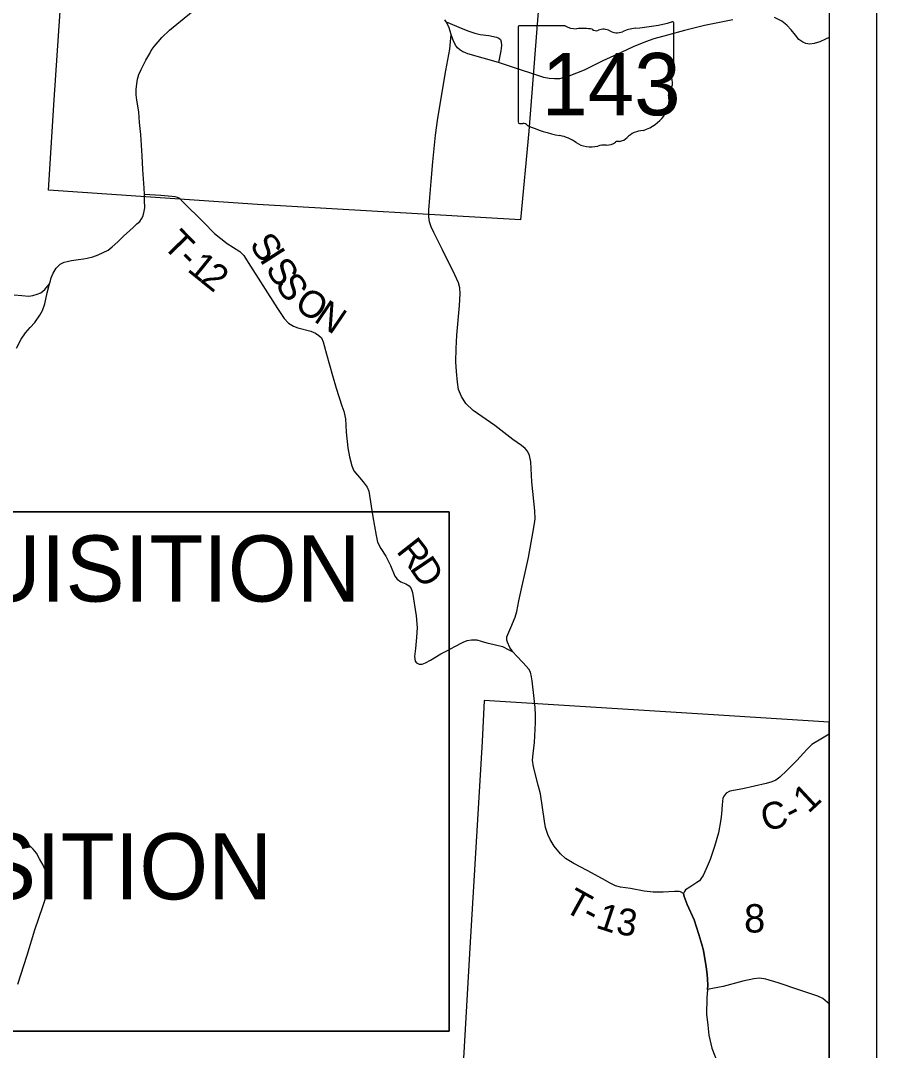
# Model space of a CAD drawing. Extents: x 0 to 34, y 0 to 22.
# Drawn here: x 7.19 to 9, y 15.883 to 18.062 of the extents above; entities that cross this region are included whole.
import ezdxf

# ---------------------------------------------------------------- set-up
doc = ezdxf.new("R2010")
doc.units = 0
for name, color, linetype in [('GM_X_Corporation', 7, 'Continuous'), ('GM_X_County_Road', 7, 'Continuous'), ('GM_X_County_Road_Text', 7, 'Continuous'), ('GM_X_Section_Text', 7, 'Continuous'), ('GM_X_State_Location', 7, 'Continuous'), ('GM_X_State_Route', 7, 'Continuous'), ('GM_X_State_Shield', 7, 'Continuous'), ('GM_X_Township_Road', 7, 'Continuous'), ('GM_X_Township_Road_Text', 7, 'Continuous'), ('SH_Data', 7, 'Continuous'), ('SH_Text', 7, 'Continuous')]:
    doc.layers.add(name, color=color, linetype=linetype)

msp = doc.modelspace()

# ---------------------------------------------------------------- linework, layer by layer
at = {"layer": 'GM_X_Corporation'}
for points in [[(7.3179, 18.7214), (8.3303, 18.6644), (8.2967, 18.2357), (8.2648, 17.8281), (8.2474, 17.6405), (7.6907, 17.673), (7.2488, 17.7032), (7.2611, 17.894), (7.2923, 18.3534)], [(8.9, 15.5562), (8.9, 16.5775), (8.644, 16.594), (8.1703, 16.6232), (8.1663, 16.5368), (8.1403, 16.1), (8.1117, 15.6084)]]:
    msp.add_lwpolyline(points, close=True, dxfattribs=at)
at = {"layer": 'GM_X_County_Road'}
for points in [[(7.4519, 17.6946), (7.4514, 17.7073), (7.4484, 17.7469), (7.4468, 17.7761), (7.4442, 17.8206), (7.4416, 17.846), (7.4398, 17.8692), (7.4358, 17.8939), (7.4342, 17.9049), (7.4346, 17.9163), (7.4358, 17.9278), (7.4374, 17.9381), (7.4402, 17.9476), (7.4449, 17.9584), (7.455, 17.9784), (7.4633, 17.9926), (7.466, 17.9986), (7.4724, 18.0074), (7.4808, 18.0172), (7.489, 18.0261), (7.5051, 18.0415), (7.528, 18.0608), (7.5551, 18.0823)], [(7.2513, 17.5047), (7.2531, 17.5116), (7.2549, 17.5176), (7.2587, 17.5274), (7.2652, 17.538), (7.2736, 17.5463), (7.2824, 17.5505), (7.2888, 17.5522), (7.2976, 17.5541), (7.3125, 17.5562), (7.3228, 17.5576), (7.3305, 17.5592), (7.3427, 17.5624), (7.3544, 17.5666), (7.3648, 17.5715), (7.3751, 17.5764), (7.384, 17.5832), (7.3954, 17.594), (7.4082, 17.6068), (7.4204, 17.6173), (7.4291, 17.6246), (7.4361, 17.6318), (7.4424, 17.637), (7.4457, 17.6426), (7.4487, 17.6477), (7.451, 17.6554), (7.4526, 17.6659), (7.4524, 17.6818), (7.4519, 17.6946)], [(7.1811, 17.3688), (7.1912, 17.3879), (7.2005, 17.4014), (7.2105, 17.4123), (7.2203, 17.4235), (7.2309, 17.4387), (7.2364, 17.4486), (7.2413, 17.4625), (7.2463, 17.4857), (7.2513, 17.5047)], [(8.9, 16.5523), (8.8858, 16.5441), (8.8634, 16.5303), (8.8536, 16.5209), (8.846, 16.5123), (8.8315, 16.4967), (8.8109, 16.4752), (8.7961, 16.4617), (8.7875, 16.4551), (8.7792, 16.4515), (8.7666, 16.4478), (8.7172, 16.4364), (8.6899, 16.4316), (8.6822, 16.4272), (8.6778, 16.422), (8.6755, 16.4168), (8.6736, 16.4025), (8.6722, 16.3841), (8.6707, 16.3719), (8.6659, 16.3439), (8.6579, 16.3145), (8.6482, 16.2875), (8.6421, 16.2724), (8.6337, 16.2532), (8.6286, 16.2461), (8.6257, 16.2419), (8.62, 16.2383), (8.6053, 16.2288), (8.5966, 16.2227), (8.5938, 16.2197), (8.5922, 16.2151)], [(7.1844, 16.0237), (7.2038, 16.0846), (7.2203, 16.1385), (7.2367, 16.188), (7.2437, 16.2065), (7.2488, 16.2243), (7.2498, 16.2357), (7.2483, 16.2462), (7.2448, 16.2588), (7.2378, 16.2753), (7.2301, 16.2889), (7.2239, 16.3003), (7.2169, 16.309), (7.2071, 16.3183), (7.1996, 16.3232), (7.1909, 16.327), (7.1802, 16.3307)], [(8.5922, 16.2151), (8.5932, 16.2088), (8.5996, 16.1917), (8.6148, 16.1598), (8.6248, 16.1285), (8.6309, 16.1074), (8.6346, 16.0946), (8.6398, 16.0599), (8.6424, 16.0436), (8.6426, 16.0341), (8.6433, 16.0212), (8.6428, 16.0121)], [(8.6428, 16.0121), (8.6415, 15.9944), (8.6407, 15.9598), (8.6432, 15.9369), (8.6456, 15.9158), (8.6518, 15.8883), (8.6643, 15.8553), (8.6681, 15.8451), (8.6695, 15.8379), (8.6687, 15.8305), (8.6671, 15.8238), (8.6624, 15.8161), (8.6534, 15.8085), (8.6369, 15.7985), (8.6126, 15.7832), (8.5958, 15.7721), (8.567, 15.7446), (8.557, 15.7324), (8.5528, 15.7256), (8.547, 15.7123), (8.5284, 15.6477), (8.5247, 15.6238), (8.522, 15.612)]]:
    msp.add_lwpolyline(points, dxfattribs=at)
at = {"layer": 'GM_X_State_Route'}
for points in [[(8.6961, 18.0633), (8.6367, 18.0516), (8.5942, 18.0408), (8.558, 18.0314), (8.5294, 18.023), (8.5117, 18.0172), (8.4858, 18.0066), (8.46, 17.9945), (8.4213, 17.9765), (8.3817, 17.9567), (8.3497, 17.9441), (8.3295, 17.9389), (8.3189, 17.9385), (8.3079, 17.9391), (8.2964, 17.9416), (8.28, 17.947), (8.2386, 17.9607), (8.2005, 17.973), (8.136, 17.9916), (8.1297, 17.9942), (8.1253, 17.9958), (8.119, 17.9997), (8.1143, 18.004), (8.1096, 18.0099), (8.1046, 18.0205), (8.101, 18.0322), (8.0965, 18.0467), (8.0931, 18.0546), (8.0901, 18.0591), (8.087, 18.0635)], [(8.9, 18.0258), (8.8927, 18.0228), (8.8803, 18.017), (8.8684, 18.0131), (8.8592, 18.012), (8.8508, 18.0134), (8.8441, 18.0165), (8.8362, 18.0219), (8.8286, 18.0311), (8.8198, 18.0426), (8.8108, 18.0525), (8.7998, 18.061), (8.7847, 18.0685)]]:
    msp.add_lwpolyline(points, dxfattribs=at)
at = {"layer": 'GM_X_State_Shield'}
for p, q in [((8.2422, 18.0476), (8.2422, 17.8475)), ((8.342, 18.051), (8.2454, 18.051)), ((8.5718, 17.9513), (8.5718, 18.056)), ((8.5718, 17.9513), (8.5718, 17.9513))]:
    msp.add_line(p, q, dxfattribs=at)
for centre, major_axis, start_param, end_param in [((8.246, 18.048), (0.00382, 0), 1.712693, 3.28349), ((8.365, 18.0742), (0.037, 0), 4.042523, 4.731795), ((8.3772, 17.9387), (0.133, 0), 1.404758, 1.657858), ((8.4074, 18.049), (0.0107, 0), 3.836095, 5.185415), ((8.4231, 18.0259), (0.0222, 0), 0.950623, 2.079405), ((8.4518, 18.0576), (0.0267, 0), 4.081561, 5.145723), ((8.499, 17.9899), (0.0703, 0), 1.699011, 2.107814), ((8.4544, 18.3238), (0.3495, 0), 4.814394, 5.042369), ((8.5681, 18.0564), (0.00367, 0), 6.141152, 7.989035), ((8.5709, 17.9436), (0.00568, 0), 1.883978, 3.671073), ((8.5348, 17.9304), (0.0341, 0), 5.934695, 6.695948), ((8.5679, 17.9509), (0.00393, 0), 5.05454, 6.418171), ((8.5849, 17.9075), (0.0248, 0), 2.387724, 3.262537), ((8.474, 17.8942), (0.0874, 0), 5.101752, 6.440018), ((8.246, 17.847), (0.00385, 0), 3.00124, 4.508301), ((8.2466, 17.8675), (0.0294, 0), 4.665946, 4.897461), ((8.2526, 17.8359), (0.0106, 0), 0.519207, 1.627899), ((8.3864, 18.0157), (0.2524, 0), 4.195997, 4.488961), ((8.5108, 17.7913), (0.0479, 0), 1.647645, 2.488434), ((8.3112, 17.7575), (0.079, 0), 0.823519, 1.323587), ((8.3966, 17.8349), (0.0501, 0), 4.026481, 4.996735), ((8.4292, 17.8199), (0.0267, 0), 4.691044, 5.507374), ((8.4534, 17.8005), (0.00752, 0), 1.147584, 2.315152), ((8.4502, 17.8281), (0.0282, 0), 4.937069, 5.64225), ((8.4256, 17.7657), (0.0412, 0), 1.495662, 1.94098)]:
    msp.add_ellipse(centre, major_axis=major_axis, ratio=0.8, start_param=start_param, end_param=end_param, dxfattribs=at)
at = {"layer": 'GM_X_Township_Road'}
for points in [[(8.0901, 18.0591), (8.1251, 18.0447), (8.1381, 18.0397), (8.1505, 18.0355), (8.1622, 18.0328), (8.1801, 18.0301), (8.1962, 18.027), (8.2018, 18.0248), (8.2049, 18.0216), (8.2067, 18.017), (8.2069, 18.0095), (8.2054, 17.998), (8.2015, 17.9767), (8.2005, 17.973)], [(8.5922, 16.2151), (8.5858, 16.2185), (8.5829, 16.2194), (8.5729, 16.2192), (8.5491, 16.2179), (8.5276, 16.2181), (8.5089, 16.2203), (8.4802, 16.2255), (8.4586, 16.2288), (8.4481, 16.2316), (8.4366, 16.2368), (8.4204, 16.2463), (8.388, 16.2637), (8.36, 16.2789), (8.3426, 16.2891), (8.3316, 16.2989), (8.3185, 16.3154), (8.3103, 16.3293), (8.3051, 16.3399), (8.3004, 16.3546), (8.2981, 16.3685), (8.2893, 16.4263), (8.2849, 16.4443), (8.2747, 16.4834), (8.2728, 16.497), (8.2738, 16.5105), (8.2767, 16.535), (8.2788, 16.5773), (8.279, 16.5928), (8.2782, 16.6084), (8.2765, 16.6279), (8.2717, 16.6652), (8.2706, 16.6733), (8.2682, 16.6835), (8.265, 16.69), (8.2526, 16.7035), (8.2389, 16.718), (8.2313, 16.7267), (8.2248, 16.736), (8.22, 16.7466), (8.2187, 16.7512), (8.2181, 16.7579), (8.2202, 16.7634), (8.2268, 16.7779), (8.2363, 16.7998), (8.2395, 16.8115), (8.2441, 16.8343), (8.2639, 16.9264), (8.2736, 16.9772), (8.2767, 16.998), (8.2782, 17.0082), (8.2777, 17.0249), (8.2713, 17.0859), (8.2689, 17.1284), (8.2663, 17.1421), (8.2623, 17.1508), (8.2574, 17.1566), (8.2495, 17.1631), (8.2313, 17.176), (8.1927, 17.2053), (8.1474, 17.2368), (8.1319, 17.2517), (8.1224, 17.2667), (8.1165, 17.2812), (8.1137, 17.2969), (8.1119, 17.3197), (8.1108, 17.3401), (8.1113, 17.3685), (8.1128, 17.3961), (8.1184, 17.4594), (8.1195, 17.4842), (8.1189, 17.4968), (8.1163, 17.507), (8.1084, 17.5239), (8.0822, 17.5766), (8.0638, 17.6139), (8.0584, 17.6258), (8.0551, 17.6361), (8.0533, 17.6467), (8.0535, 17.6606), (8.0557, 17.6875), (8.0583, 17.7218), (8.0616, 17.7628), (8.0676, 17.8195), (8.0726, 17.8555), (8.0891, 17.956), (8.0976, 18.0015), (8.101, 18.0322)], [(7.2513, 17.5047), (7.2531, 17.5116), (7.2549, 17.5176), (7.2587, 17.5274), (7.2652, 17.538), (7.2736, 17.5463), (7.2824, 17.5505), (7.2888, 17.5522), (7.2976, 17.5541), (7.3125, 17.5562), (7.3228, 17.5576), (7.3305, 17.5592), (7.3427, 17.5624), (7.3544, 17.5666), (7.3648, 17.5715), (7.3751, 17.5764), (7.384, 17.5832), (7.3954, 17.594), (7.4082, 17.6068), (7.4204, 17.6173), (7.4291, 17.6246), (7.4361, 17.6318), (7.4424, 17.637), (7.4457, 17.6426), (7.4487, 17.6477), (7.451, 17.6554), (7.4526, 17.6659), (7.4524, 17.6818), (7.4519, 17.6946)], [(7.4519, 17.6946), (7.4864, 17.6925), (7.5098, 17.6904), (7.5159, 17.6899), (7.5212, 17.6887), (7.5261, 17.686), (7.5334, 17.6785), (7.5767, 17.6357), (7.6003, 17.6112), (7.6267, 17.5902), (7.6536, 17.5731), (7.6625, 17.565), (7.6713, 17.5502), (7.7337, 17.453), (7.7475, 17.4318), (7.7563, 17.422), (7.7673, 17.4156), (7.7766, 17.4122), (7.8042, 17.4046), (7.814, 17.4006), (7.8209, 17.396), (7.8266, 17.391), (7.8302, 17.3824), (7.8371, 17.356), (7.8497, 17.3112), (7.8574, 17.2843), (7.8693, 17.2471), (7.8736, 17.2359), (7.8774, 17.2197), (7.8788, 17.1911), (7.8819, 17.1578), (7.8857, 17.1389), (7.8905, 17.1199), (7.8945, 17.1096), (7.9145, 17.0858), (7.9229, 17.0748), (7.9262, 17.0663), (7.9348, 17.0124), (7.9417, 16.9726), (7.945, 16.9583), (7.952, 16.945), (7.9624, 16.9288), (7.972, 16.9088), (7.9815, 16.8868), (7.9865, 16.8804), (7.9944, 16.8749), (8.0046, 16.8704), (8.012, 16.8659), (8.0158, 16.8602), (8.0187, 16.8521), (8.0265, 16.8025), (8.0287, 16.778), (8.0272, 16.7565), (8.0251, 16.7334), (8.0234, 16.7165), (8.0244, 16.7069), (8.0275, 16.7029), (8.033, 16.7005), (8.0392, 16.7005), (8.0464, 16.7029), (8.0567, 16.709), (8.0785, 16.722), (8.093, 16.7291), (8.1087, 16.7377), (8.1259, 16.7473), (8.1342, 16.7508), (8.1435, 16.752), (8.1547, 16.7517), (8.1642, 16.7491), (8.1762, 16.7458), (8.1919, 16.742), (8.209, 16.7379), (8.2226, 16.7305), (8.2313, 16.7267)], [(7.1763, 17.4815), (7.1926, 17.48), (7.2071, 17.4791), (7.2161, 17.4803), (7.2248, 17.4833), (7.233, 17.4863), (7.2413, 17.4933), (7.2513, 17.5047)], [(8.6428, 16.0121), (8.6433, 16.0212), (8.6426, 16.0341), (8.6424, 16.0436), (8.6398, 16.0599), (8.6346, 16.0946), (8.6309, 16.1074), (8.6248, 16.1285), (8.6148, 16.1598), (8.5996, 16.1917), (8.5932, 16.2088), (8.5922, 16.2151)], [(8.9, 15.9816), (8.8967, 15.9848), (8.8868, 15.9934), (8.876, 15.9982), (8.8631, 16.0025), (8.8358, 16.0118), (8.7925, 16.0262), (8.7665, 16.0343), (8.7531, 16.036), (8.7405, 16.0345), (8.7175, 16.0295), (8.6756, 16.0187), (8.6532, 16.0141), (8.6428, 16.0121)]]:
    msp.add_lwpolyline(points, dxfattribs=at)
at = {"layer": 'SH_Data'}
for p, q in [((9, 21), (9, 14)), ((8.9, 20.9), (8.9, 14.1))]:
    msp.add_line(p, q, dxfattribs=at)
at = {"layer": 'SH_Text'}
for points in [[(8.0965, 17.0228), (6.0206, 17.0228), (6.0206, 15.9239), (8.0965, 15.9239)], [(6.0206, 17.0228), (8.0965, 17.0228), (8.0965, 15.9239), (6.0206, 15.9239)]]:
    msp.add_lwpolyline(points, close=True, dxfattribs=at)

# ---------------------------------------------------------------- texts
at = {"layer": 'GM_X_County_Road_Text'}
for s, rotation, p in [('1', 42.9818, (8.8563, 16.3832)), ('C', 15.1439, (8.7644, 16.3458)), ('-', 27.2708, (8.8216, 16.3627))]:
    msp.add_text(s, height=0.0568, rotation=rotation, dxfattribs=at).set_placement(p)
at = {"layer": 'GM_X_Section_Text'}
msp.add_text('8', height=0.06, rotation=0, dxfattribs=at).set_placement((8.7202, 16.1327))
at = {"layer": 'GM_X_State_Location'}
for s in ['s', 'r']:
    msp.add_text(s, height=0.000189, dxfattribs=at).set_placement((8.4033, 17.9342))
msp.add_text('143', height=0.000189, rotation=0, dxfattribs=at).set_placement((8.3364, 17.9204))
at = {"layer": 'GM_X_State_Shield'}
msp.add_text('143', height=0.13184, dxfattribs=at).set_placement((8.2917, 17.8616))
at = {"layer": 'GM_X_Township_Road_Text'}
for s, rotation, p in [('T', 314.0212, (7.4884, 17.5854)), ('S', 305.0489, (7.6723, 17.5878)), ('I', 302.6789, (7.6939, 17.5569)), ('-', 315.5734, (7.5191, 17.5536)), ('1', 321.0747, (7.5403, 17.5334)), ('2', 321.2522, (7.5676, 17.5112)), ('S', 302.5211, (7.7065, 17.5373)), ('S', 302.5269, (7.7271, 17.505)), ('O', 327.0589, (7.7663, 17.454)), ('N', 325.8735, (7.808, 17.427)), ('R', 308.2368, (7.9831, 16.939)), ('D', 304.0457, (8.0114, 16.9032)), ('T', 331.0078, (8.3361, 16.1798)), ('1', 341.6345, (8.4043, 16.1436)), ('-', 331.9053, (8.3741, 16.1587)), ('3', 351.0208, (8.4474, 16.1301))]:
    msp.add_text(s, height=0.0568, rotation=rotation, dxfattribs=at).set_placement(p)
at = {"layer": 'SH_Text'}
for s, p in [('BEGIN ACQUISITION', (6.0576, 16.8328)), ('END ACQUISITION', (6.0576, 16.2028))]:
    msp.add_text(s, height=0.14, dxfattribs=at).set_placement(p)

doc.saveas('drawing.dxf')
